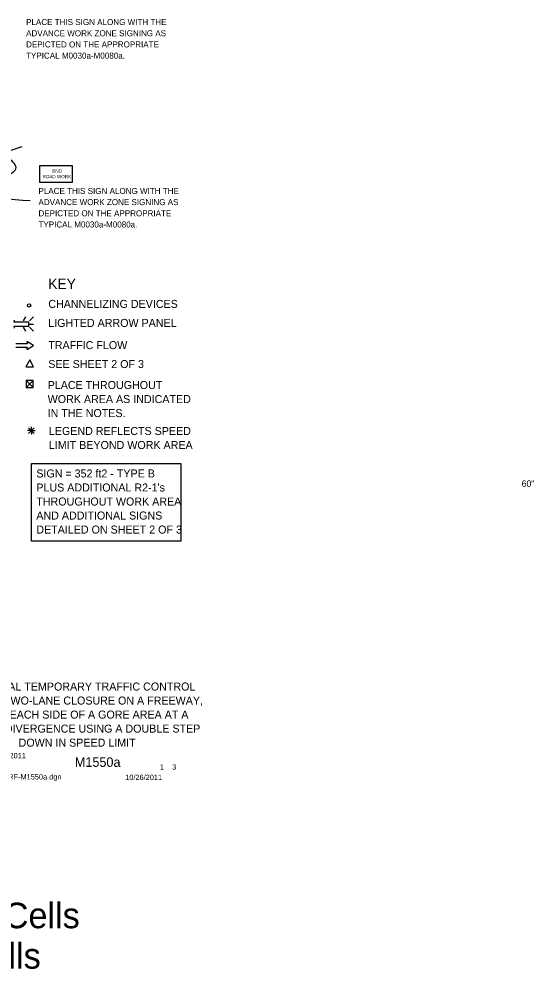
# Model space of a CAD drawing. Extents: x 16452 to 19508, y 5713 to 7079.
# Drawn here: x 17224 to 17823, y 5713 to 6818 of the extents above; entities that cross this region are included whole.
import ezdxf

# ---------------------------------------------------------------- set-up
doc = ezdxf.new("R2010")
doc.units = 0
for name, color, linetype in [('BORDER', 7, 'Continuous'), ('BORDER_SIGNAL_WO', 7, 'Continuous'), ('MT_SCRATCH_LEVEL_E', 7, 'Continuous'), ('PAVT_EDGE_EX', 7, 'Continuous'), ('TRAFFIC_SIGNS_PR', 7, 'Continuous'), ('TYPICAL_TEXT_DIMEN_EX', 7, 'Continuous'), ('TYPICAL_TEXT_DIMEN_PR', 7, 'Continuous')]:
    doc.layers.add(name, color=color, linetype=linetype)

msp = doc.modelspace()

# ---------------------------------------------------------------- linework, layer by layer
at = {"layer": 'MT_SCRATCH_LEVEL_E'}
for p, q in [((17233.7, 6440.1), (17220.5, 6440.1)), ((17233.4, 6441.9), (17233.7, 6440.1)), ((17241.3, 6438.3), (17234.1, 6442.4)), ((17220.5, 6436.4), (17233.7, 6436.4)), ((17233.7, 6436.4), (17233.4, 6434.6)), ((17234.1, 6434.1), (17241.3, 6438.3))]:
    msp.add_line(p, q, dxfattribs=at)
for centre, start, end in [((17233.9, 6442), 60.4248, 189.9638), ((17233.9, 6434.5), 170.0362, 299.7731)]:
    msp.add_arc(centre, 0.463, start, end, dxfattribs=at)
at = {"layer": 'PAVT_EDGE_EX'}
msp.add_arc((17319.9, 6383.8), 300, 107.923, 180, dxfattribs=at)
at = {"layer": 'TRAFFIC_SIGNS_PR'}
for p, q in [((17229.5, 6466.7), (17232.3, 6471.6)), ((17236.4, 6466.7), (17241.3, 6471.6)), ((17236.4, 6463.2), (17241.3, 6463.2)), ((17232.4, 6454.7), (17229.5, 6459.6)), ((17236.4, 6459.6), (17241.3, 6454.7))]:
    msp.add_line(p, q, dxfattribs=at)
msp.add_lwpolyline([(17248.1, 6628), (17286.5, 6628), (17286.5, 6647.2), (17248.1, 6647.2)], close=True, dxfattribs=at)
msp.add_lwpolyline([(17219.1, 6458.5), (17218.7, 6460.7), (17235.7, 6460.7), (17235.7, 6465.5), (17218.7, 6465.5), (17219.1, 6467.8)], dxfattribs=at)
msp.add_circle((17236.1, 6484.8), 2, dxfattribs=at)
at = {"layer": 'TYPICAL_TEXT_DIMEN_EX'}
msp.add_lwpolyline([(17238.7, 6301.2), (17412.4, 6301.2), (17412.4, 6210.9), (17238.7, 6210.9)], close=True, dxfattribs=at)
at = {"layer": 'TYPICAL_TEXT_DIMEN_PR'}
for p, q in [((17232.8, 6397.5), (17240.8, 6389.5)), ((17232.8, 6389.5), (17240.8, 6397.5)), ((17238.7, 6339.3), (17234.2, 6339.3)), ((17235.5, 6342.5), (17241.9, 6336.1)), ((17241.9, 6342.5), (17235.5, 6336.1)), ((17238.7, 6339.3), (17238.7, 6343.7)), ((17238.7, 6339.3), (17241.9, 6339.3)), ((17238.7, 6339.3), (17243.2, 6339.3)), ((17238.7, 6339.3), (17238.7, 6334.8))]:
    msp.add_line(p, q, dxfattribs=at)
for points in [[(17236.8, 6421.5), (17232.3, 6413.6), (17241.4, 6413.6)], [(17232.8, 6397.5), (17232.8, 6389.5), (17240.8, 6389.5), (17240.8, 6397.5)]]:
    msp.add_lwpolyline(points, close=True, dxfattribs=at)
msp.add_open_spline([(17211.5, 6657), (17216.4, 6652.5), (17226.4, 6643.1), (17205.5, 6632.6), (17175.7, 6610.9), (17212.4, 6608.3), (17237.4, 6606.6)], degree=3, dxfattribs=at)

# ---------------------------------------------------------------- texts
at = {"layer": 'BORDER'}
for s, p in [('TYPICAL TEMPORARY TRAFFIC CONTROL', (17175.2, 6037.1)), ('FOR A TWO-LANE CLOSURE ON A FREEWAY,', (17165.4, 6020.8)), ('ONE ON EACH SIDE OF A GORE AREA AT A ', (17160.9, 6004.5)), ('MAJOR DIVERGENCE USING A DOUBLE STEP ', (17160.9, 5988.2)), ('DOWN IN SPEED LIMIT', (17223.9, 5971.9))]:
    msp.add_text(s, height=9.3, dxfattribs=at).set_placement(p)
at = {"layer": 'BORDER_SIGNAL_WO'}
for s, height, p in [('    OCTOBER 2011    ', 6.2, (17159.1, 5958.3)), ('    M1550a   ', 11, (17272.9, 5948.4)), (' 1    3 ', 6.2, (17385.9, 5945.2)), ('k:-DGN-TSR-STDS-ENGLISH-MNTTRF-M1550a.dgn      ', 6.2, (17070.6, 5933.7)), ('10/26/2011    ', 6.2, (17347.9, 5933.1)), ('AS = 0.8 for Sign Cells', 29.727, (16894, 5760.8)), ('     1.0 for Text Cells', 29.727, (16894, 5713.8))]:
    msp.add_text(s, height=height, dxfattribs=at).set_placement(p)
at = {"layer": 'TRAFFIC_SIGNS_PR'}
for s, height, p in [('PLACE THIS SIGN ALONG WITH THE', 7, (17232.6, 6810.7)), ('ADVANCE WORK ZONE SIGNING AS', 7, (17232.6, 6797.7)), ('DEPICTED ON THE APPROPRIATE', 7, (17232.6, 6784.7)), ('TYPICAL M0030a-M0080a.', 7, (17232.6, 6771.7)), ('END', 3.83, (17263.1, 6639.1)), ('ROAD WORK', 3.83, (17251.7, 6632.7)), ('PLACE THIS SIGN ALONG WITH THE', 7, (17247, 6614.4)), ('ADVANCE WORK ZONE SIGNING AS', 7, (17247, 6601.4)), ('DEPICTED ON THE APPROPRIATE', 7, (17247, 6588.4)), ('TYPICAL M0030a-M0080a.', 7, (17247, 6575.4))]:
    msp.add_text(s, height=height, dxfattribs=at).set_placement(p)
at = {"layer": 'TYPICAL_TEXT_DIMEN_EX'}
for s, height, p in [('KEY', 12, (17258.4, 6503.9)), ('CHANNELIZING DEVICES', 9.3, (17258.4, 6481.9)), ('LIGHTED ARROW PANEL', 9.3, (17258.4, 6459.8)), ('TRAFFIC FLOW', 9.3, (17258.4, 6434)), ('SEE SHEET 2 OF 3', 9.3, (17258.4, 6412)), ('PLACE THROUGHOUT', 9.3, (17257.7, 6387.6)), ('WORK AREA AS INDICATED', 9.3, (17257.7, 6371.3)), ('IN THE NOTES.', 9.3, (17257.7, 6355)), ('LEGEND REFLECTS SPEED', 9.3, (17259.1, 6334.2)), ('LIMIT BEYOND WORK AREA', 9.3, (17259.1, 6317.9)), ('SIGN = 352 ft2 - TYPE B', 9.3, (17244.5, 6284.8)), ("PLUS ADDITIONAL R2-1's", 9.3, (17244.5, 6268.5)), ('THROUGHOUT WORK AREA', 9.3, (17244.5, 6252.2)), ('AND ADDITIONAL SIGNS', 9.3, (17244.5, 6235.9)), ('DETAILED ON SHEET 2 OF 3', 9.3, (17244.5, 6219.6))]:
    msp.add_text(s, height=height, dxfattribs=at).set_placement(p)
at = {"layer": 'TYPICAL_TEXT_DIMEN_PR'}
msp.add_text('60"', height=7.55, dxfattribs=at).set_placement((17808.9, 6273.9))

doc.saveas('drawing.dxf')
